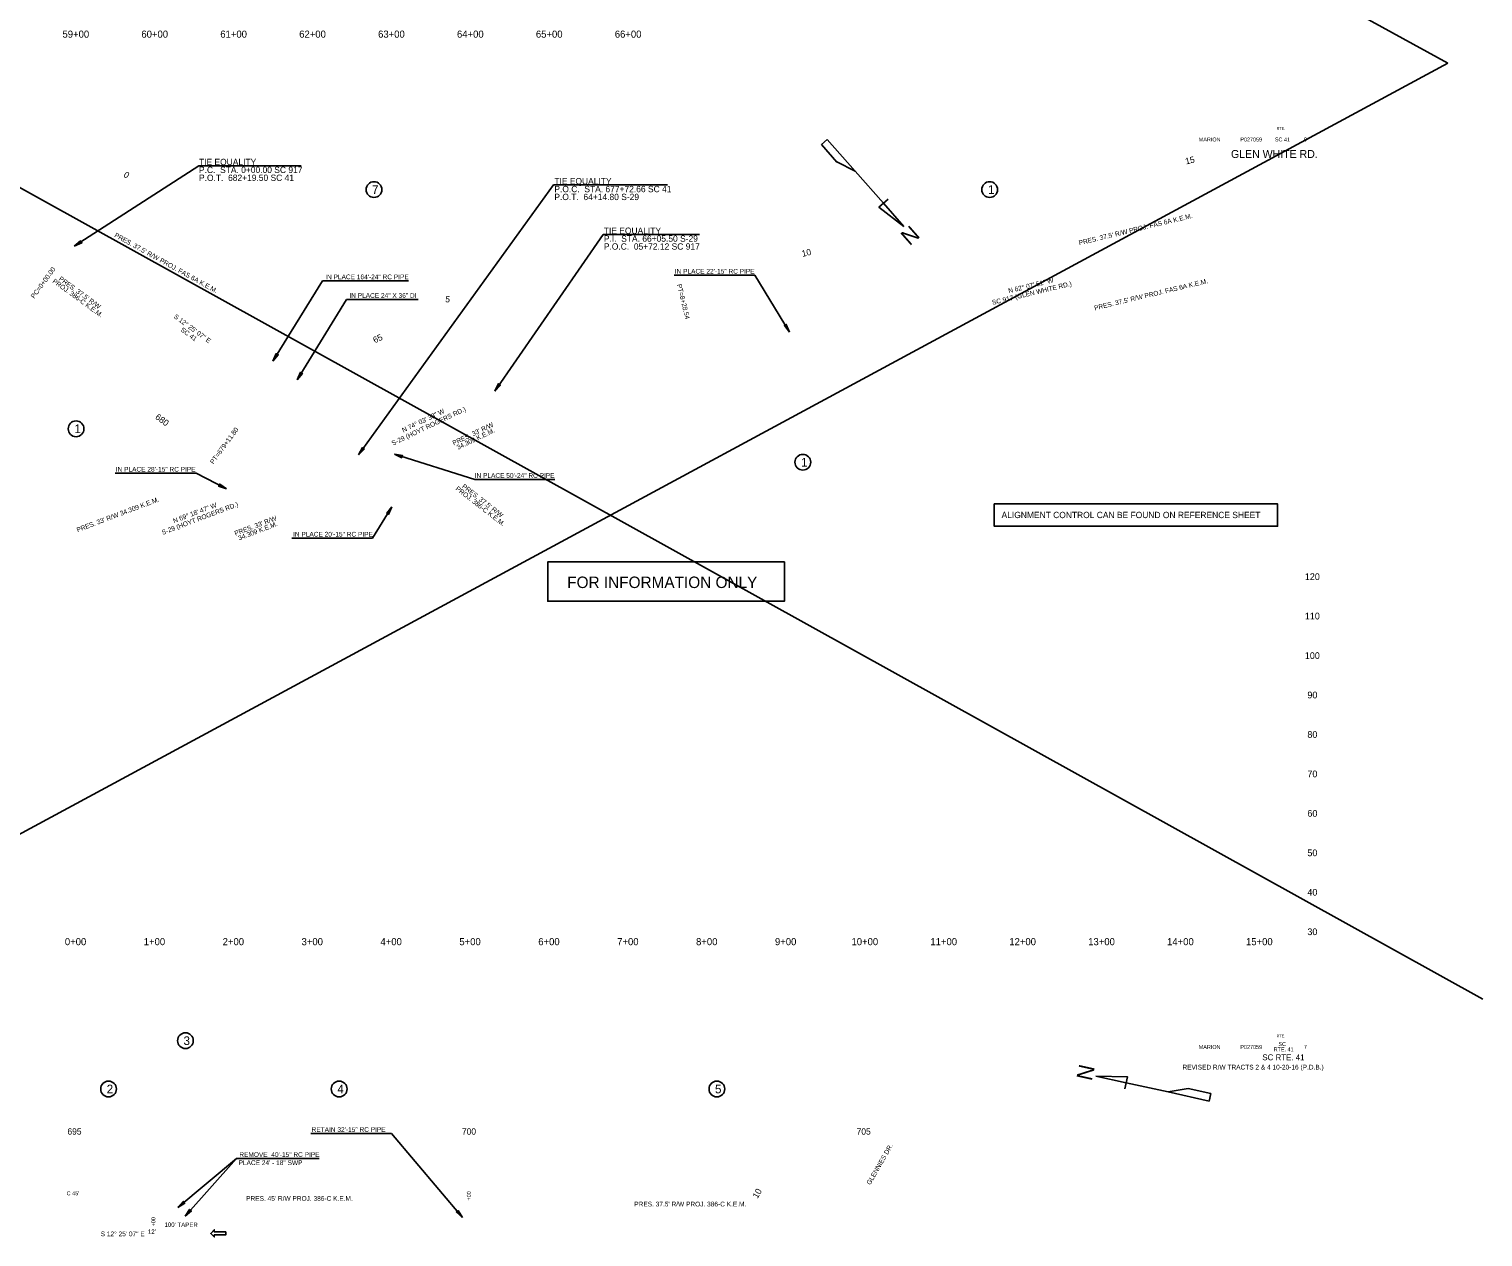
# Model space of a CAD drawing. Extents: x 2522404 to 2525275, y 885432 to 893540.
# Drawn here: x 2523355 to 2525198, y 889756 to 891287 of the extents above; entities that cross this region are included whole.
import ezdxf

# ---------------------------------------------------------------- set-up
doc = ezdxf.new("R2010")
doc.units = 0
for name, color, linetype in [('Default', 7, 'Continuous'), ('GN_Clip', 7, 'Continuous'), ('RD_DDB_ElevTX', 7, 'Continuous'), ('RD_DDB_Profile_EX', 7, 'Continuous'), ('RD_DDB_Profile_Lbl', 7, 'Continuous'), ('RD_DDB_Profile_PR', 7, 'Continuous'), ('RD_DDB_StaTX', 7, 'Continuous'), ('RD_EX_Misc', 7, 'Continuous'), ('RD_HC_Cl', 7, 'Continuous'), ('RD_HC_TX_Sta50', 7, 'Continuous'), ('RD_HY_TX1', 7, 'Continuous'), ('RD_PD_Final_LnLine', 7, 'Continuous'), ('RD_PD_RW_TX', 7, 'Continuous'), ('RD_PD_TX_CstnLmt', 7, 'Continuous'), ('RD_SHT_IplotShp', 7, 'Continuous'), ('RD_Sketch1', 7, 'Continuous'), ('RD_Sketch8', 7, 'Continuous'), ('RD_TX_Profile', 7, 'Continuous')]:
    doc.layers.add(name, color=color, linetype=linetype)

# ---------------------------------------------------------------- blocks, each defined once
blk = doc.blocks.new('ah_')
at = {"layer": 'Default'}
blk.add_lwpolyline([(0, 0), (-1.4, -10.4), (0, -8.8), (1.5, -10.4)], close=True, dxfattribs=at)
blk = doc.blocks.new('ah4')
at = {"layer": 'Default', "rotation": -90.00000000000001}
blk.add_blockref('ah_', (0, 0), dxfattribs=at)
blk = doc.blocks.new('AH4_')
at = {"layer": 'Default'}
blk.add_lwpolyline([(0, 0), (-10.4, 1.5), (-8.8, 0), (-10.4, -1.5)], close=True, dxfattribs=at)

msp = doc.modelspace()

# ---------------------------------------------------------------- linework, layer by layer
at = {"layer": 'Default'}
msp.add_lwpolyline([(2523604.5, 889762.9), (2523604.5, 889759.1), (2523589.9, 889759.1), (2523589.9, 889756.5), (2523585.4, 889761), (2523589.9, 889765.5), (2523589.9, 889762.9)], close=True, dxfattribs=at)
at = {"layer": 'RD_DDB_ElevTX'}
for p, q in [((2523105.6, 892369.2), (2525153.6, 891243.7)), ((2523069.4, 890119.2), (2525153.6, 891243.7)), ((2523089.9, 891226.7), (2525197.9, 890057.9))]:
    msp.add_line(p, q, dxfattribs=at)
at = {"layer": 'RD_DDB_Profile_PR'}
msp.add_lwpolyline([(2524578.5, 890685.3), (2524578.5, 890656.9), (2524937.6, 890656.9), (2524937.6, 890685.3)], close=True, dxfattribs=at)
at = {"layer": 'RD_EX_Misc'}
for centre in [(2523792.4, 891083.6), (2524572.7, 891083.6), (2523414.8, 890780.5), (2524335.9, 890738.1), (2523553.4, 890005.1), (2523456, 889943.9), (2523748.3, 889943.9), (2524227, 889943.9)]:
    msp.add_circle(centre, 10, dxfattribs=at)
at = {"layer": 'RD_HY_TX1'}
for p, q in [((2523814.8, 889887.4), (2523904.6, 889780.9)), ((2523543.6, 889793.6), (2523618.2, 889855.7)), ((2523552.9, 889782.7), (2523618.2, 889855.7))]:
    msp.add_line(p, q, dxfattribs=at)
for points in [[(2524274.9, 890975), (2524172.9, 890975)], [(2524319.2, 890903.1), (2524274.9, 890975)], [(2523664.4, 890866.2), (2523727, 890967.9)], [(2523836, 890967.9), (2523727, 890967.9)], [(2523695, 890842.6), (2523757.6, 890944.3)], [(2523848.5, 890944.3), (2523757.6, 890944.3)], [(2523920, 890716.2), (2523818.2, 890748.4)], [(2523567, 890724.1), (2523464.3, 890724.1)], [(2523605.4, 890704.4), (2523567, 890724.1)], [(2524021.8, 890716.2), (2523920, 890716.2)], [(2523790.7, 890641.9), (2523815.2, 890681.7)], [(2523790.7, 890641.9), (2523688.4, 890641.9)], [(2523814.8, 889887.4), (2523712.2, 889887.4)], [(2523723.1, 889855.7), (2523618.2, 889855.7)]]:
    msp.add_lwpolyline(points, dxfattribs=at)
at = {"layer": 'RD_PD_RW_TX'}
for p, q in [((2523412.6, 891011.8), (2523570.2, 891113.7)), ((2523570.2, 891113.7), (2523700.3, 891113.7)), ((2523772.9, 890747.5), (2524020.1, 891089.5)), ((2524020.1, 891089.5), (2524164.5, 891089.5)), ((2523945.5, 890828.3), (2524082.8, 891026.6)), ((2524082.8, 891026.6), (2524205, 891026.6))]:
    msp.add_line(p, q, dxfattribs=at)
at = {"layer": 'RD_Sketch8'}
for p, q in [((2524366.9, 891147.2), (2524359.5, 891140.7)), ((2524359.5, 891140.7), (2524379.1, 891118.5)), ((2524402.2, 891107.1), (2524366.9, 891147.2)), ((2524379, 891118.7), (2524402.2, 891107.1)), ((2524379.1, 891118.5), (2524379, 891118.7)), ((2524402.2, 891107.1), (2524438.2, 891066.4)), ((2524438.2, 891066.4), (2524432.3, 891061.2)), ((2524432.3, 891061.2), (2524432.6, 891060.8)), ((2524432.3, 891061.2), (2524464.1, 891037)), ((2524444.1, 891071.5), (2524438.2, 891066.4)), ((2524464.1, 891037), (2524438.2, 891066.4)), ((2524464.1, 891037), (2524464.1, 891037)), ((2524747.3, 889959.5), (2524707.4, 889960.2)), ((2524707.4, 889960.2), (2524707.4, 889960.2)), ((2524707.4, 889960.2), (2524745.6, 889951.8)), ((2524745.6, 889951.8), (2524747.3, 889959.5)), ((2524747.3, 889959.5), (2524746.9, 889959.6)), ((2524744, 889944.1), (2524745.6, 889951.8)), ((2524798.8, 889940.1), (2524745.6, 889951.8)), ((2524824.3, 889944.5), (2524798.8, 889940.1)), ((2524798.8, 889940.1), (2524850.9, 889928.6)), ((2524853, 889938.2), (2524824.1, 889944.6)), ((2524824.1, 889944.6), (2524824.3, 889944.5)), ((2524850.9, 889928.6), (2524853, 889938.2))]:
    msp.add_line(p, q, dxfattribs=at)
at = {"layer": 'RD_TX_Profile'}
msp.add_lwpolyline([(2524312.6, 890611.9), (2524012.6, 890611.9), (2524012.6, 890561.9), (2524312.6, 890561.9)], close=True, dxfattribs=at)

# ---------------------------------------------------------------- block references
at = {"layer": 'RD_HY_TX1'}
for p, rotation in [((2524319.2, 890903.1), -58.65092228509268), ((2523605.4, 890704.4), -27.500116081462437), ((2523543.6, 889793.6), -140.25828125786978), ((2523904.6, 889780.9), -50.10998641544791)]:
    msp.add_blockref('ah4', p, dxfattribs=dict(at, rotation=rotation))
for p, yscale, rotation in [((2523664.4, 890866.2), -0.9999999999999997, -121.34907771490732), ((2523695, 890842.6), -0.9999999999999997, -121.34907771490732), ((2523818.2, 890748.4), -0.9999999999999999, 162.72525879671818), ((2523815.2, 890681.7), -0.9999999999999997, 58.65092228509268), ((2523552.9, 889782.7), -0.9999999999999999, -131.53637984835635)]:
    msp.add_blockref('ah4', p, dxfattribs=dict(at, yscale=yscale, rotation=rotation))
at = {"layer": 'RD_PD_Final_LnLine'}
for p, rotation in [((2523412.6, 891011.8), -147.38200284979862), ((2523945.5, 890828.3), -124.96742511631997), ((2523772.8, 890747.3), -126.05139297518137)]:
    msp.add_blockref('AH4_', p, dxfattribs=dict(at, rotation=rotation))

# ---------------------------------------------------------------- texts
at = {"layer": 'Default'}
msp.add_text('FOR INFORMATION ONLY', height=14.542, dxfattribs=at).set_placement((2524037.3, 890578.7))
at = {"layer": 'GN_Clip'}
for s, p in [('59+00', (2523397.6, 891276.1)), ('60+00', (2523497.6, 891276.1)), ('61+00', (2523597.6, 891276.1)), ('62+00', (2523697.6, 891276.1)), ('63+00', (2523797.6, 891276.1)), ('64+00', (2523897.6, 891276.1)), ('65+00', (2523997.6, 891276.1)), ('66+00', (2524097.6, 891276.1)), ('0+00', (2523400.6, 890126.1)), ('1+00', (2523500.6, 890126.1)), ('2+00', (2523600.6, 890126.1)), ('3+00', (2523700.6, 890126.1)), ('4+00', (2523800.6, 890126.1)), ('5+00', (2523900.6, 890126.1)), ('6+00', (2524000.6, 890126.1)), ('7+00', (2524100.6, 890126.1)), ('8+00', (2524200.6, 890126.1)), ('9+00', (2524300.6, 890126.1)), ('10+00', (2524397.6, 890126.1)), ('11+00', (2524497.6, 890126.1)), ('12+00', (2524597.6, 890126.1)), ('13+00', (2524697.6, 890126.1)), ('14+00', (2524797.6, 890126.1)), ('15+00', (2524897.6, 890126.1))]:
    msp.add_text(s, height=9, dxfattribs=at).set_placement(p)
at = {"layer": 'RD_DDB_Profile_EX'}
for s, rotation, p in [('15', 13.5527, (2524821.7, 891115.4)), ('0', 323.8405, (2523474, 891100.7)), ('10', 13.5527, (2524335.6, 890998.3)), ('5', 353.8405, (2523882.4, 890941)), ('65', 25.4824, (2523793.5, 890888.7)), ('680', 323.8405, (2523514.3, 890793.8)), ('10', 60.077, (2524278.5, 889804.5))]:
    msp.add_text(s, height=8, rotation=rotation, dxfattribs=at).set_placement(p)
for s, p in [('695', (2523403.9, 889886.1)), ('700', (2523903.9, 889886.1)), ('705', (2524404.1, 889886.1))]:
    msp.add_text(s, height=8, dxfattribs=at).set_placement(p)
at = {"layer": 'RD_DDB_Profile_Lbl'}
for s, p in [('7', (2523789.9, 891078.1)), ('1', (2524570.6, 891078.1)), ('1', (2523412.7, 890775)), ('1', (2524333.8, 890732.6)), ('3', (2523551, 889999.6)), ('2', (2523453.6, 889938.4)), ('4', (2523746, 889938.4)), ('5', (2524224.6, 889938.4))]:
    msp.add_text(s, height=11, dxfattribs=at).set_placement(p)
at = {"layer": 'RD_DDB_Profile_PR'}
msp.add_text('ALIGNMENT CONTROL CAN BE FOUND ON REFERENCE SHEET', height=8, dxfattribs=at).set_placement((2524587.8, 890667.3))
at = {"layer": 'RD_DDB_StaTX'}
for s, p in [("100' TAPER", (2523526.8, 889769.2)), ("12'", (2523505.8, 889760.4))]:
    msp.add_text(s, height=5.6, rotation=359.5861, dxfattribs=at).set_placement(p)
at = {"layer": 'RD_EX_Misc'}
for s, height, p in [('RTE.', 3.5, (2524936.3, 891159.3)), ('MARION', 5, (2524837.7, 891144.6)), ('P027059', 5, (2524890.4, 891144.6)), ('SC 41', 5, (2524934.2, 891144.6)), ('9', 5, (2524970.9, 891144.6)), ('GLEN WHITE RD.', 10, (2524878.6, 891123.7)), ('RTE.', 3.5, (2524936.3, 890009.3)), ('MARION', 5, (2524837.7, 889994.6)), ('P027059', 5, (2524890.4, 889994.6)), ('RTE. 41', 5, (2524932.6, 889991.6)), ('SC ', 5, (2524938.7, 889998.3)), ('7', 5, (2524971, 889994.6)), ('SC RTE. 41', 7.5, (2524918.3, 889980.3))]:
    msp.add_text(s, height=height, dxfattribs=at).set_placement(p)
at = {"layer": 'RD_HC_Cl'}
for s, height, rotation, p in [('TIE EQUALITY', 8, 360, (2523570.6, 891114.6)), ('P.C.  STA. 0+00.00 SC 917', 8, 360, (2523570.6, 891104.6)), ('P.O.T.  682+19.50 SC 41', 8, 360, (2523570.6, 891094.6)), ('TIE EQUALITY', 8, 360, (2524021, 891090.3)), ('P.O.C.  STA. 677+72.66 SC 41', 8, 360, (2524021, 891080.3)), ('P.O.T.  64+14.80 S-29', 8, 360, (2524021, 891070.3)), ('TIE EQUALITY', 8, 360, (2524083.7, 891027.5)), ('P.I.  STA. 66+05.50 S-29', 8, 360, (2524083.7, 891017.5)), ('P.O.C.  05+72.12 SC 917', 8, 360, (2524083.7, 891007.5)), ('PC=0+00.00', 6, 53.8405, (2523361.7, 890945)), ('N 62%%d 07\' 51" W', 6, 13.5527, (2524597.1, 890952.3)), ('PT=8+28.54', 6, 283.5527, (2524176.3, 890963.2)), ('SC 917 (GLEN WHITE RD.)', 6, 13.5527, (2524576.5, 890937.5)), ('S 12%%d 25\' 07" E', 6, 323.8405, (2523538, 890921.5)), ('SC 41', 6, 323.8405, (2523546.7, 890904.7)), ('S-29 (HOYT ROGERS RD.)', 6, 25.4824, (2523816.4, 890759)), ('N 74%%d 03\' 38" W', 6, 25.4824, (2523829.6, 890775.7)), ('PT=679+11.80', 6, 53.8405, (2523588.8, 890735.2)), ('S-29 (HOYT ROGERS RD.)', 6, 20.7351, (2523524.6, 890646)), ('N 69%%d 18\' 47" W', 6, 20.7351, (2523539, 890660.8)), ('GLENNIES DR.', 6, 60.077, (2524421.4, 889821.8)), ('S 12%%d 25\' 07" E', 6, 360, (2523446, 889757.3))]:
    msp.add_text(s, height=height, rotation=rotation, dxfattribs=at).set_placement(p)
at = {"layer": 'RD_HC_TX_Sta50'}
for s, p in [('120', (2524972.2, 890588.9)), ('110', (2524972.2, 890538.9)), ('100', (2524972.2, 890488.9)), ('90', (2524975.4, 890438.9)), ('80', (2524975.4, 890388.9)), ('70', (2524975.4, 890338.9)), ('60', (2524975.4, 890288.9)), ('50', (2524975.4, 890238.9)), ('40', (2524975.4, 890188.9)), ('30', (2524975.4, 890138.9))]:
    msp.add_text(s, height=8.5, dxfattribs=at).set_placement(p)
at = {"layer": 'RD_HY_TX1'}
for s, p in [('IN PLACE 164\'-24" RC PIPE', (2523730.6, 890970)), ('IN PLACE 22\'-15" RC PIPE', (2524173.6, 890977.1)), ('IN PLACE 24" X 36" DI', (2523761.2, 890946.4)), ('IN PLACE 28\'-15" RC PIPE', (2523465.1, 890726.2)), ('IN PLACE 50\'-24" RC PIPE', (2523920, 890718.3)), ('IN PLACE 20\'-15" RC PIPE', (2523689.8, 890643.9)), ('RETAIN 32\'-15" RC PIPE', (2523713.3, 889889.5)), ('REMOVE  40\'-15" RC PIPE', (2523621.7, 889857.8)), ('PLACE 24\' - 18" SWP', (2523620.8, 889847.5))]:
    msp.add_text(s, height=6, dxfattribs=at).set_placement(p)
at = {"layer": 'RD_PD_TX_CstnLmt'}
msp.add_text("C 45'", height=5, dxfattribs=at).set_placement((2523402.9, 889809.2))
at = {"layer": 'RD_SHT_IplotShp'}
for s, height, rotation, p in [("PRES. 37.5' R/W PROJ. FAS 6A K.E.M.", 6, 13.5527, (2524686.4, 891013.1)), ("PRES. 37.5' R/W PROJ. FAS 6A K.E.M.", 6, 330.8771, (2523462.8, 891024)), ('PROJ. 386-C K.E.M.', 6, 323.8405, (2523384.3, 890966.3)), ("PRES. 37.5' R/W", 6, 323.8405, (2523392.3, 890969.3)), ("PRES. 37.5' R/W PROJ. FAS 6A K.E.M.", 6, 13.5527, (2524706, 890930.5)), ("PRES. 33' R/W", 6, 25.4824, (2523893.6, 890759.3)), ('34.309 K.E.M.', 6, 25.4824, (2523898.9, 890753.8)), ("PRES. 37.5' R/W", 6, 322.1543, (2523903.3, 890706.4)), ("PRES. 33' R/W 34.309 K.E.M.", 6, 20.7574, (2523416.8, 890649.3)), ('PROJ. 386-C K.E.M.', 6, 322.1543, (2523895.2, 890703.5)), ("PRES. 33' R/W", 6, 20.7574, (2523616.9, 890644.9)), ('34.309 K.E.M.', 6, 20.7574, (2523621.7, 890639)), ("PRES. 45' R/W PROJ. 386-C K.E.M.", 6, 360, (2523630.4, 889802.2)), ('+00', 5, 90, (2523915.1, 889802.6)), ("PRES. 37.5' R/W PROJ. 386-C K.E.M.", 6, 360, (2524122.3, 889795.1)), ('+00', 5, 90, (2523515.3, 889769.8))]:
    msp.add_text(s, height=height, rotation=rotation, dxfattribs=at).set_placement(p)
at = {"layer": 'RD_Sketch1'}
msp.add_text('REVISED R/W TRACTS 2 & 4 10-20-16 (P.D.B.)', height=6, rotation=360, dxfattribs=at).set_placement((2524817, 889968.6))
at = {"layer": 'RD_Sketch8'}
for rotation, p in [(221.422, (2524472.5, 891039.4)), (77.5815, (2524702, 889953.3))]:
    msp.add_text('N', height=20, rotation=rotation, dxfattribs=at).set_placement(p)

doc.saveas('drawing.dxf')
